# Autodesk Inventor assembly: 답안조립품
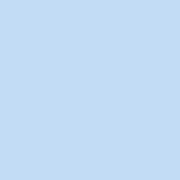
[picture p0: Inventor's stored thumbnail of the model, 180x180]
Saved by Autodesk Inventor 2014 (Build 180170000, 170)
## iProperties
Created: 2025-06
Part Number: 답안조립품
Document SubType Name: Assembly
Designer: dg
Author: dg
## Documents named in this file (1)
- C:\Users\dg\Desktop\750603V1012\답안조립품.iam
